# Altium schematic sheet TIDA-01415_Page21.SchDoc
size 431 x 279 mm; Date: Not shown in title block; ApprovedBy: Not shown in title block; CheckedBy: Not shown in title block; Author: Not shown in title block; CompanyName: Not shown in title block; Engineer: Not shown in title block; Organization: Not shown in title block; Address1: Not shown in title block; Address2: Not shown in title block; Address3: Not shown in title block; Address4: Not shown in title block; DocumentNumber: 1; Revision: Use project parameter SCH_Rev; SheetNumber: 3; SheetTotal: 6; PageSetup: Record=PageOptions¦CenterHorizontal=True¦CenterVertical=True¦PrintScale=1.00¦XCorrection=1.00¦YCorrection=1.00¦PrintKind=0¦BorderSize=5000000¦LeftOffset=0¦BottomOffset=0¦Orientation=2¦PaperLength=1000¦PaperWidth=1000¦Scale=100¦PaperSource=15¦PrintQuality=600¦MediaType=1¦DitherType=10¦PaperKind=Letter¦PrintScaleMode=1
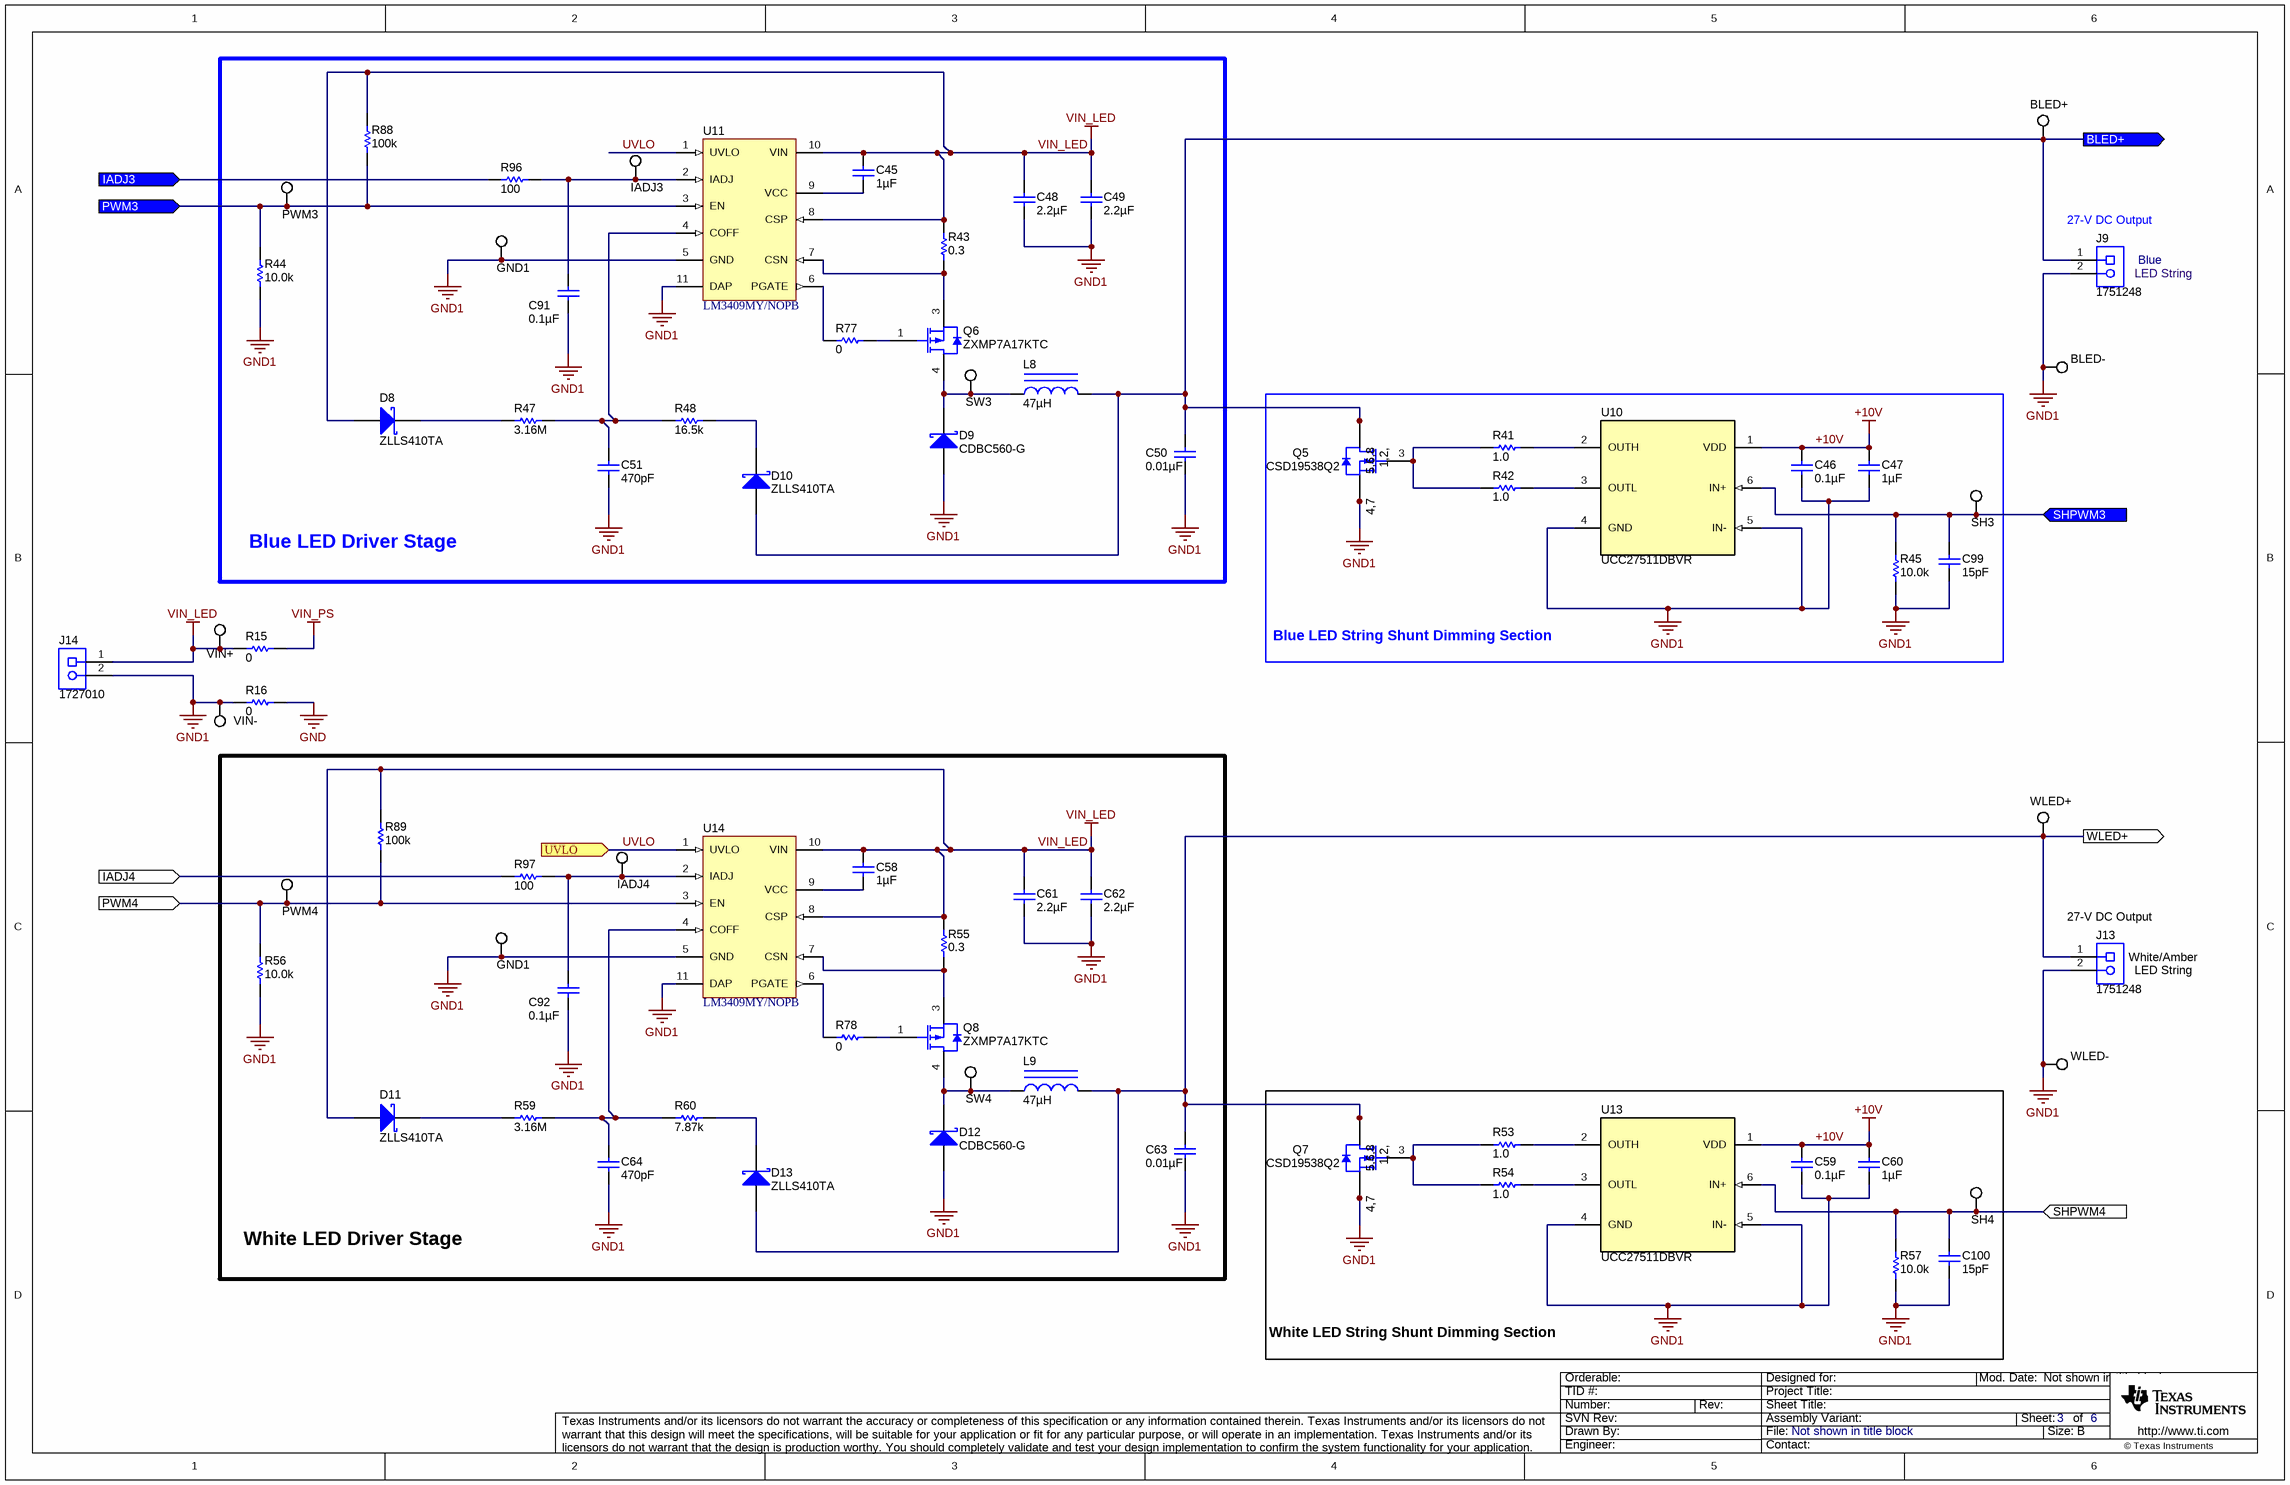
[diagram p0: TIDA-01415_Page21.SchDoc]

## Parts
(Parts that share a designator on the sheet are numbered #1, #2 ... from top to bottom, then left to right.)
BLED+  5015  [Testpoint_Keystone_Miniature]  (value not drawn)
BLED-  5015  [Testpoint_Keystone_Miniature]  (value not drawn)
C45  ValueDisplayed: 1µF  [0603]  (hidden comment: C1608X7R1C105K080AC)
C46  ValueDisplayed: 0.1µF  [0805_HV]  (hidden comment: C2012X7R1H104K085AA)
C47  ValueDisplayed: 1µF  [0805_HV]  (hidden comment: C2012X7R1H105K125AB)
C48  ValueDisplayed: 2.2µF  [0805_HV]  (hidden comment: C2012X7R1H225K125AC)
C49  ValueDisplayed: 2.2µF  [0805_HV]  (hidden comment: C2012X7R1H225K125AC)
C50  ValueDisplayed: 0.01µF  [0805_HV]  (hidden comment: 885012207092)
C51  ValueDisplayed: 470pF  [0201_033]  (hidden comment: CGA1A2X7R1H471K030BA)
C58  ValueDisplayed: 1µF  [0603]  (hidden comment: C1608X7R1C105K080AC)
C59  ValueDisplayed: 0.1µF  [0805_HV]  (hidden comment: C2012X7R1H104K085AA)
C60  ValueDisplayed: 1µF  [0805_HV]  (hidden comment: C2012X7R1H105K125AB)
C61  ValueDisplayed: 2.2µF  [0805_HV]  (hidden comment: C2012X7R1H225K125AC)
C62  ValueDisplayed: 2.2µF  [0805_HV]  (hidden comment: C2012X7R1H225K125AC)
C63  ValueDisplayed: 0.01µF  [0805_HV]  (hidden comment: 885012207092)
C64  ValueDisplayed: 470pF  [0201_033]  (hidden comment: CGA1A2X7R1H471K030BA)
C91  ValueDisplayed: 0.1µF  [0402]  (hidden comment: C1005X7R1E104M050BB)
C92  ValueDisplayed: 0.1µF  [0402]  (hidden comment: C1005X7R1E104M050BB)
C99  ValueDisplayed: 15pF  [0402]  (hidden comment: 885012005056)
C100  ValueDisplayed: 15pF  [0402]  (hidden comment: 885012005056)
D8  ZLLS410TA  [SOD-323]
D9  CDBC560-G  [SMC]
D10  ZLLS410TA  [SOD-323]
D11  ZLLS410TA  [SOD-323]
D12  CDBC560-G  [SMC]
D13  ZLLS410TA  [SOD-323]
GND1#1  5015  [Testpoint_Keystone_Miniature]  (value not drawn)
GND1#2  5015  [Testpoint_Keystone_Miniature]  (value not drawn)
IADJ3  5015  [Testpoint_Keystone_Miniature]  (value not drawn)
IADJ4  5015  [Testpoint_Keystone_Miniature]  (value not drawn)
J9  1751248  [CONN_1751248]
J13  1751248  [CONN_1751248]
J14  1727010  [PhoenixConact_1727010]
L8  ValueDisplayed: 47µH  [WE-PD_1280]  (hidden comment: 744770147)
L9  ValueDisplayed: 47µH  [WE-PD_1280]  (hidden comment: 744770147)
PWM3  5015  [Testpoint_Keystone_Miniature]  (value not drawn)
PWM4  5015  [Testpoint_Keystone_Miniature]  (value not drawn)
Q5  CSD19538Q2  [DQK0006C]
Q6  ZXMP7A17KTC  [DPAK]
Q7  CSD19538Q2  [DQK0006C]
Q8  ZXMP7A17KTC  [DPAK]
R15  ValueDisplayed: 0  [0402]  (hidden comment: CRCW04020000Z0ED)
R16  ValueDisplayed: 0  [0402]  (hidden comment: CRCW04020000Z0ED)
R41  ValueDisplayed: 1.0  [0603]  (hidden comment: CRCW06031R00JNEA)
R42  ValueDisplayed: 1.0  [0603]  (hidden comment: CRCW06031R00JNEA)
R43  ValueDisplayed: 0.3  [2512]  (hidden comment: CSRN2512FKR300)
R44  ValueDisplayed: 10.0k  [0603]  (hidden comment: CRCW060310K0FKEA)
R45  ValueDisplayed: 10.0k  [0603]  (hidden comment: CRCW060310K0FKEA)
R47  ValueDisplayed: 3.16M  [0603]  (hidden comment: CRCW06033M16FKEA)
R48  ValueDisplayed: 16.5k  [0603]  (hidden comment: CRCW060316K5FKEA)
R53  ValueDisplayed: 1.0  [0603]  (hidden comment: CRCW06031R00JNEA)
R54  ValueDisplayed: 1.0  [0603]  (hidden comment: CRCW06031R00JNEA)
R55  ValueDisplayed: 0.3  [2512]  (hidden comment: CSRN2512FKR300)
R56  ValueDisplayed: 10.0k  [0603]  (hidden comment: CRCW060310K0FKEA)
R57  ValueDisplayed: 10.0k  [0603]  (hidden comment: CRCW060310K0FKEA)
R59  ValueDisplayed: 3.16M  [0603]  (hidden comment: CRCW06033M16FKEA)
R60  ValueDisplayed: 7.87k  [0603]  (hidden comment: CRCW06037K87FKEA)
R77  ValueDisplayed: 0  [0603]  (hidden comment: CRCW06030000Z0EA)
R78  ValueDisplayed: 0  [0603]  (hidden comment: CRCW06030000Z0EA)
R88  ValueDisplayed: 100k  [0603]  (hidden comment: CRCW0603100KFKEA)
R89  ValueDisplayed: 100k  [0603]  (hidden comment: CRCW0603100KFKEA)
R96  ValueDisplayed: 100  [0603]  (hidden comment: RC0603FR-07100RL)
R97  ValueDisplayed: 100  [0603]  (hidden comment: RC0603FR-07100RL)
SH3  5015  [Testpoint_Keystone_Miniature]  (value not drawn)
SH4  5015  [Testpoint_Keystone_Miniature]  (value not drawn)
SW3  5015  [Testpoint_Keystone_Miniature]  (value not drawn)
SW4  5015  [Testpoint_Keystone_Miniature]  (value not drawn)
U10  UCC27511DBVR  [DBV0006A_N]
U11  LM3409MY/NOPB  [MUC10A_N]
U13  UCC27511DBVR  [DBV0006A_N]
U14  LM3409MY/NOPB  [MUC10A_N]
VIN+  5015  [Testpoint_Keystone_Miniature]  (value not drawn)
VIN-  5015  [Testpoint_Keystone_Miniature]  (value not drawn)
WLED+  5015  [Testpoint_Keystone_Miniature]  (value not drawn)
WLED-  5015  [Testpoint_Keystone_Miniature]  (value not drawn)

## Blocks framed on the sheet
Blue LED Driver Stage: C45 C48-C51 C91 D8-D10 GND1#1 IADJ3 L8 PWM3 Q6 R43 R44 R47 R48 R77 R88 R96 SW3 U11
Blue LED String Shunt Dimming Section: C46 C47 C99 Q5 R41 R42 R45 SH3 U10
White LED Driver Stage: C58 C61-C64 C92 D11-D13 GND1#2 IADJ4 L9 PWM4 Q8 R55 R56 R59 R60 R78 R89 R97 SW4 U14
White LED String Shunt Dimming Section: C59 C60 C100 Q7 R53 R54 R57 SH4 U13

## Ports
BLED+ (out), IADJ3 (in), IADJ4 (in), PWM3 (in), PWM4 (in), SHPWM3 (in), SHPWM4 (in), UVLO (in), WLED+ (out)

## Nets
+10V: C46.1 C47.1 C59.1 C60.1 U10.1(VDD) U13.1(VDD)
GND: R16.2
GND1: BLED-.1 C46.2 C47.2 C48.2 C49.2 C50.2 C51.2 C59.2 C60.2 C61.2 C62.2 C63.2 C64.2 C91.1 C92.1 C99.2 C100.2 D9.2(A) D12.2(A) GND1#1.1 GND1#2.1 J9.2 J13.2 J14.2 Q5.4(S) Q5.7(S) Q7.4(S) Q7.7(S) R16.1 R44.1 R45.1 R56.1 R57.1 U10.4(GND) U10.5(IN-) U11.5(GND) U11.11(DAP) U13.4(GND) U13.5(IN-) U14.5(GND) U14.11(DAP) VIN-.1 WLED-.1
VIN_LED: C45.1 C48.1 C49.1 C58.1 C61.1 C62.1 D8.2(A) D11.2(A) J14.1 R15.1 R43.2 R55.2 R88.2 R89.2 U11.8(CSP) U11.10(VIN) U14.8(CSP) U14.10(VIN) VIN+.1
VIN_PS: R15.2
BLED+: BLED+.1 C50.1 D10.2(A) J9.1 L8.2 Q5.1(D) Q5.2(D) Q5.5(D) Q5.6(D) Q5.8(D) ; port BLED+
IADJ3: R96.2 ; port IADJ3
IADJ4: R97.2 ; port IADJ4
PWM3: PWM3.1 R44.2 R88.1 U11.3(EN) ; port PWM3
PWM4: PWM4.1 R56.2 R89.1 U14.3(EN) ; port PWM4
SHPWM3: C99.1 R45.2 SH3.1 U10.6(IN+) ; port SHPWM3
SHPWM4: C100.1 R57.2 SH4.1 U13.6(IN+) ; port SHPWM4
UVLO: U11.1(UVLO) U14.1(UVLO) ; port UVLO
WLED+: C63.1 D13.2(A) J13.1 L9.2 Q7.1(D) Q7.2(D) Q7.5(D) Q7.6(D) Q7.8(D) WLED+.1 ; port WLED+
NetC45_2: C45.2 U11.9(VCC)
NetC51_1: C51.1 R47.2 R48.1 U11.4(COFF)
NetC58_2: C58.2 U14.9(VCC)
NetC64_1: C64.1 R59.2 R60.1 U14.4(COFF)
NetC91_2: C91.2 IADJ3.1 R96.1 U11.2(IADJ)
NetC92_2: C92.2 IADJ4.1 R97.1 U14.2(IADJ)
NetD8_1: D8.1(K) R47.1
NetD9_1: D9.1(K) L8.1 Q6.4(D) SW3.1
NetD10_1: D10.1(K) R48.2
NetD11_1: D11.1(K) R59.1
NetD12_1: D12.1(K) L9.1 Q8.4(D) SW4.1
NetD13_1: D13.1(K) R60.2
NetQ5_3: Q5.3(G) R41.1 R42.1
NetQ6_1: Q6.1(G) R77.2
NetQ6_3: Q6.3(S) R43.1 U11.7(CSN)
NetQ7_3: Q7.3(G) R53.1 R54.1
NetQ8_1: Q8.1(G) R78.2
NetQ8_3: Q8.3(S) R55.1 U14.7(CSN)
NetR41_2: R41.2 U10.2(OUTH)
NetR42_2: R42.2 U10.3(OUTL)
NetR53_2: R53.2 U13.2(OUTH)
NetR54_2: R54.2 U13.3(OUTL)
NetR77_1: R77.1 U11.6(PGATE)
NetR78_1: R78.1 U14.6(PGATE)

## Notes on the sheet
- (near J9) 27-V DC Output
- (near J9) Blue
- (near J9) LED String
- (near J13) 27-V DC Output
- (near J13) White/Amber
- (near J13) LED String

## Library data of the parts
BLED+ BLED- GND1#1 GND1#2 IADJ3 IADJ4 PWM3 PWM4 SH3 SH4 SW3 SW4 VIN+ VIN- WLED+ WLED- = 5015: Test Point, Miniature, SMT; Manufacturer: Keystone; CompType: Test Point Loop
C45 C58 = C1608X7R1C105K080AC: CAP, CERM, 1 µF, 16 V, +/- 10%, X7R, 0603; Manufacturer: TDK; Polarized: N; CompType: Capacitor; Value: 1uF; U/M: EA; Cap_F: 0.000001; Tolerance_%: 10; ESR_ohm: 0.0057; Value1: 0.0057 ohm; VDC_V: 16; Value2: 16V; TaMin_C: -55; TaMax_C: 125; SizeArea_mm2: 1.28; SizeAreaWB_mm2: 4.68; SizeX_mm: 1.6; SizeY_mm: 0.8; SizeZ_mm: 1; AEC Category: Q200
C46 C59 = C2012X7R1H104K085AA: CAP, CERM, 0.1 µF, 50 V, +/- 10%, X7R, 0805; Manufacturer: TDK; Polarized: N; CompType: Capacitor; Value: 0.1uF; U/M: EA; Cap_F: 0.0000001; Tolerance_%: 10; ESR_ohm: 0.02619; Value1: 0.02619 ohm; VDC_V: 50; Value2: 50V; IRMS_A: 1.29514; TaMin_C: -55; TaMax_C: 125; Cap_Case: 0805; SizeArea_mm2: 2.5; SizeAreaWB_mm2: 6.75; SizeX_mm: 2; SizeY_mm: 1.25; SizeZ_mm: 1.45; AEC Category: Q200
C47 C60 = C2012X7R1H105K125AB: CAP, CERM, 1 µF, 50 V, +/- 10%, X7R, 0805; Manufacturer: TDK; Polarized: N; CompType: Capacitor; Value: 1uF; U/M: EA; Cap_F: 0.000001; Tolerance_%: 10; ESR_ohm: 0.008782; Value1: 0.008782 ohm; VDC_V: 50; Value2: 50V; IRMS_A: 2.20488; TaMin_C: -55; TaMax_C: 125; Cap_Case: 0805; SizeArea_mm2: 2.5; SizeAreaWB_mm2: 6.75; SizeX_mm: 2; SizeY_mm: 1.25; SizeZ_mm: 1.45; AEC Category: Q200
C48 C49 C61 C62 = C2012X7R1H225K125AC: CAP, CERM, 2.2 µF, 50 V, +/- 10%, X7R, 0805; Manufacturer: TDK; Polarized: N; CompType: Capacitor; Value: 2.2uF; U/M: EA; Cap_F: 0.0000022; Tolerance_%: 10; ESR_ohm: 0.00366; Value1: 0.00366 ohm; VDC_V: 50; Value2: 50V; IRMS_A: 3.41207; TaMin_C: -55; TaMax_C: 125; Cap_Case: 0805; SizeArea_mm2: 2.5; SizeAreaWB_mm2: 6.75; SizeX_mm: 2; SizeY_mm: 1.25; SizeZ_mm: 1.45; AEC Category: Q200
C50 C63 = 885012207092: CAP, CERM, 0.01 µF, 50 V, +/- 10%, X7R, 0805; Manufacturer: Wurth Elektronik; Polarized: N; CompType: Capacitor; Value: 0.01uF; U/M: EA; Cap_F: 0.00000001; Tolerance_%: 10; Value1: Unknown; VDC_V: 50; Value2: 50V; TaMin_C: -55; TaMax_C: 125; Cap_Case: 0805; SizeArea_mm2: 2.5; SizeAreaWB_mm2: 6.75; SizeX_mm: 2; SizeY_mm: 1.25; SizeZ_mm: 1.45; AEC Category: Q200
C51 C64 = CGA1A2X7R1H471K030BA: CAP, CERM, 470 pF, 50 V, +/- 10%, X7R, AEC-Q200 Grade 1, 0201; Manufacturer: TDK; Polarized: N; CompType: Capacitor; Value: 470pF; U/M: EA; Cap_F: 0.00000000047; Tolerance_%: 10; ESR_ohm: 5.54785; Value1: 5.54785 ohm; VDC_V: 50; Value2: 50V; IRMS_A: 0.228855; TaMin_C: -55; TaMax_C: 125; SizeArea_mm2: 0.18; SizeAreaWB_mm2: 2.08; SizeX_mm: 0.6; SizeY_mm: 0.3; SizeZ_mm: 0.33; AEC Category: Q200; AEC Qualified: Y; AEC Grade: 1
C91 C92 = C1005X7R1E104M050BB: CAP, CERM, 0.1 µF, 25 V, +/- 20%, X7R, 0402; Manufacturer: TDK; Polarized: N; CompType: Capacitor; Value: 0.1uF; U/M: EA; Cap_F: 0.0000001; Tolerance_%: 20; Value1: Unknown; VDC_V: 25; Value2: 25V; TaMin_C: -55; TaMax_C: 125; SizeArea_mm2: 0.5; SizeAreaWB_mm2: 3; SizeX_mm: 1; SizeZ_mm: 0.6; AEC Category: Q200
C99 C100 = 885012005056: CAP, CERM, 15 pF, 50 V, +/- 5%, C0G/NP0, 0402; Manufacturer: Wurth Elektronik; Polarized: N; CompType: Capacitor; Value: 15pF; U/M: EA; Cap_F: 0.000000000015; Tolerance_%: 5; Value1: Unknown; VDC_V: 50; Value2: 50V; TaMin_C: -55; TaMax_C: 125; SizeArea_mm2: 0.5; SizeAreaWB_mm2: 3; SizeX_mm: 1; SizeZ_mm: 0.6; AEC Category: Q200
D8 D10 D11 D13 = ZLLS410TA: Diode, Schottky, 10 V, 0.75 A, SOD-323; Manufacturer: Diodes Inc.; U/M: EA; Value: 10V; Value1: 0.75A; Io_A: 0.75; Vr_V: 10; TJmax_C: 150; SizeAreaWB_mm2: 8.695; SizeArea_mm2: 3.645; SizeX_mm: 2.7; SizeY_mm: 1.35; SizeZ_mm: 1; AEC Category: Q101; AEC Qualified: N
D9 D12 = CDBC560-G: Diode, Schottky, 60 V, 5 A, SMC; Manufacturer: Comchip Technology; U/M: EA; Vf_V: 0.75; Value: 60V; Value1: 5A; Value2: 0.75V; Io_A: 5; Vr_V: 60; TJmax_C: 125; SizeAreaWB_mm2: 83.2686; SizeArea_mm2: 50.5686; SizeX_mm: 8.13; SizeY_mm: 6.22; SizeZ_mm: 2.6; AEC Category: Q101
J9 J13 = 1751248: Conn Term Block, 2POS, 3.5mm, TH; Manufacturer: Phoenix Contact; SymbolCreator: a0412235; CompType: Terminal Block
J14 = 1727010: Conn Term Block, 2POS, 3.81mm, TH; Manufacturer: Phoenix Contact; SymbolCreator: a0412235; CompType: Terminal Block
L8 L9 = 744770147: Inductor, Shielded Drum Core, Ferrite, 47 µH, 2.7 A, 0.076 ohm, SMD; Manufacturer: Wurth Elektronik; Value: 47uH; Ind_H: 47.0E-6; Imax_A: 2.7; Irms: 2.7A @ 40C rise; Isat: 3A @ 10% inductance drop; DCR_ohm: 0.076; Value2: 2.7A; SizeAreaWB_mm2: 196; SizeArea_mm2: 144; SizeX_mm: 12; SizeZ_mm: 8; AEC Category: Q200
Q5 Q7 = CSD19538Q2: MOSFET, N-CH, 100 V, 4.5 A, DQK0006C (WSON-6); Manufacturer: Texas Instruments; Alternate Manufacturer: None; U/M: EA; ChType: N; Value: 100V; VdsMax_V: 100; Value1: ? ohm; Value2: ? nC; Vgs_V: 20; IdsMax_A: 4.5; SizeAreaWB_mm2: 9; SizeArea_mm2: 4; SizeX_mm: 2; SizeZ_mm: 0.8; AEC Category: Q101
Q6 Q8 = ZXMP7A17KTC: MOSFET, P-CH, -70 V, -5.7 A, DPAK; Manufacturer: Diodes Inc.; Alternate Manufacturer: None; U/M: EA; ChType: P; Value: -70V; Value1: 0.25 ohm; Rdson45_ohm: 0.25; Value2: 18 nC; QgTyp_nC: 18; Vgs_V: -20; SizeAreaWB_mm2: 101.7114; SizeArea_mm2: 64.8114; SizeX_mm: 9.91; SizeY_mm: 6.54; SizeZ_mm: 2.29; AEC Category: Q101; AEC Qualified: N
R15 R16 = CRCW04020000Z0ED: RES, 0, 5%, 0.063 W, 0402; Manufacturer: Vishay-Dale; CompType: Resistor; Value: 0; Value_Code: 0000; Tolerance_%: 5; Power_W: 0.063; Value2: 0.063W; VDC_V: 50; TempCo: 200 ppm/C; SizeArea_mm2: 0.5; SizeX_mm: 1; SizeZ_mm: 0.6; EIA_Code: E24; U/M: EA; AEC Category: Q200
R41 R42 R53 R54 = CRCW06031R00JNEA: RES, 1.0, 5%, 0.1 W, 0603; Manufacturer: Vishay-Dale; CompType: Resistor; Value: 1.0; Res_ohm: 1; Value_Code: 1R00; Tolerance_%: 5; Power_W: 0.1; Value2: 0.1W; VDC_V: 75; TempCo: 200 ppm/C; SizeArea_mm2: 1.28; SizeX_mm: 1.6; SizeY_mm: 0.8; EIA_Code: E24; U/M: EA; AEC Category: Q200
R43 R55 = CSRN2512FKR300: RES, 0.3, 1%, 2 W, 2512; Manufacturer: Stackpole Electronics Inc; CompType: Resistor; Value: 0.3; Value_Code: R300; Tolerance_%: 1; Power_W: 2; Value2: 2W; TempCo: 200 ppm/C; SizeArea_mm2: 20.16; SizeX_mm: 6.3; SizeY_mm: 3.2; SizeZ_mm: 0.71; EIA_Code: E96; U/M: EA; AEC Category: Q200
R44 R45 R56 R57 = CRCW060310K0FKEA: RES, 10.0 k, 1%, 0.1 W, 0603; Manufacturer: Vishay-Dale; CompType: Resistor; Value: 10.0k; Res_ohm: 10000; Value_Code: 10k0; Tolerance_%: 1; Power_W: 0.1; Value2: 0.1W; VDC_V: 75; TempCo: 100 ppm/C; SizeArea_mm2: 1.28; SizeX_mm: 1.6; SizeY_mm: 0.8; EIA_Code: E96; U/M: EA; AEC Category: Q200
R47 R59 = CRCW06033M16FKEA: RES, 3.16 M, 1%, 0.1 W, 0603; Manufacturer: Vishay-Dale; CompType: Resistor; Value: 3.16Meg; Res_ohm: 3160000; Value_Code: 3M16; Tolerance_%: 1; Power_W: 0.1; Value2: 0.1W; VDC_V: 75; TempCo: 100 ppm/C; SizeArea_mm2: 1.28; SizeX_mm: 1.6; SizeY_mm: 0.8; EIA_Code: E96; U/M: EA; AEC Category: Q200
R48 = CRCW060316K5FKEA: RES, 16.5 k, 1%, 0.1 W, 0603; Manufacturer: Vishay-Dale; CompType: Resistor; Value: 16.5k; Res_ohm: 16500; Value_Code: 16k5; Tolerance_%: 1; Power_W: 0.1; Value2: 0.1W; VDC_V: 75; TempCo: 100 ppm/C; SizeArea_mm2: 1.28; SizeX_mm: 1.6; SizeY_mm: 0.8; EIA_Code: E96; U/M: EA; AEC Category: Q200
R60 = CRCW06037K87FKEA: RES, 7.87 k, 1%, 0.1 W, 0603; Manufacturer: Vishay-Dale; CompType: Resistor; Value: 7.87k; Res_ohm: 7870; Value_Code: 7k87; Tolerance_%: 1; Power_W: 0.1; Value2: 0.1W; VDC_V: 75; TempCo: 100 ppm/C; SizeArea_mm2: 1.28; SizeX_mm: 1.6; SizeY_mm: 0.8; EIA_Code: E96; U/M: EA; AEC Category: Q200
R77 R78 = CRCW06030000Z0EA: RES, 0, 5%, 0.1 W, 0603; Manufacturer: Vishay-Dale; CompType: Resistor; Value: 0; Value_Code: 0000; Tolerance_%: 5; Power_W: 0.1; Value2: 0.1W; VDC_V: 75; TempCo: 200 ppm/C; SizeArea_mm2: 1.28; SizeX_mm: 1.6; SizeY_mm: 0.8; SizeZ_mm: 1; EIA_Code: E24; U/M: EA; AEC Category: Q200
R88 R89 = CRCW0603100KFKEA: RES, 100 k, 1%, 0.1 W, 0603; Manufacturer: Vishay-Dale; CompType: Resistor; Value: 100k; Res_ohm: 100000; Tolerance_%: 1; Power_W: 0.1; Value2: 0.1W; VDC_V: 75; TempCo: 100 ppm/C; SizeArea_mm2: 1.28; SizeX_mm: 1.6; SizeY_mm: 0.8; EIA_Code: E96; U/M: EA; AEC Category: Q200
R96 R97 = RC0603FR-07100RL: RES, 100, 1%, 0.1 W, 0603; Manufacturer: Yageo America; CompType: Resistor; Value: 100; Value_Code: 100R; Tolerance_%: 1; Power_W: 0.1; Value2: 0.1W; VDC_V: 150; TempCo: 200 ppm/C; SizeArea_mm2: 1.28; SizeX_mm: 1.6; SizeY_mm: 0.8; EIA_Code: E96; U/M: EA; AEC Category: Q200
U10 U13 = UCC27511DBVR: Single-Channel High-Speed Low-Side Gate Driver (with 4-A Peak Source and 8-A Peak Sink), DBV0006A (SOT-6); Alternate PartNumber: UCC27511DBVT; Manufacturer: Texas Instruments; SymbolCreator: a0411947; SizeArea_mm2: 8.12; SizeAreaWB_mm2: 14.82; SizeX_mm: 2.8; SizeY_mm: 2.9; SizeZ_mm: 1.45; CompType: IC; U/M: EA
U11 U14 = LM3409MY/NOPB: PFET Buck Controller for High Power LED Drives, 10-pin eMSOP, Pb-Free; Manufacturer: Texas Instruments; PackageTopMarking: ZXTT*SXFB; PowerWise: Y; CompType: MiscPower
